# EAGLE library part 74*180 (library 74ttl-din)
9-bit odd/even PARITY GENERATOR/CHECKER
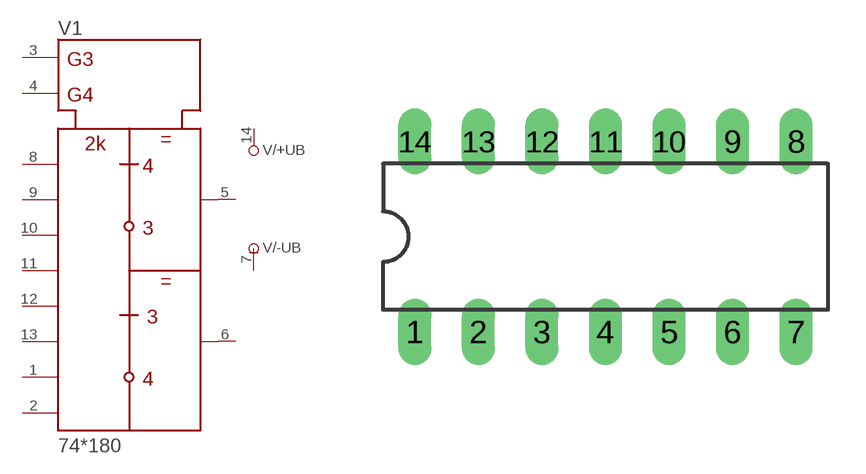
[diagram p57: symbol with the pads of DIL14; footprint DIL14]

Designator prefix V; gates /+UB=+UB /-UB=-UB 1=180

## 74180N  [DIL14]
1  1:G  in
2  1:H  in
3  1:EVEN  in
4  1:ODD  in
5  1:SEVEN  out
6  1:SODD  out
7  /-UB:-UB  pwr
8  1:A  in
9  1:B  in
10  1:C  in
11  1:D  in
12  1:E  in
13  1:F  in
14  /+UB:+UB  pwr

## Footprint DIL14 (pad centres in mm)
Dual In Line Package
drill 0.813 long: 1 -7.62,-3.81; 2 -5.08,-3.81; 3 -2.54,-3.81; 4 0,-3.81; 5 2.54,-3.81; 6 5.08,-3.81; 7 7.62,-3.81; 8 7.62,3.81; 9 5.08,3.81; 10 2.54,3.81; 11 0,3.81; 12 -2.54,3.81; 13 -5.08,3.81; 14 -7.62,3.81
